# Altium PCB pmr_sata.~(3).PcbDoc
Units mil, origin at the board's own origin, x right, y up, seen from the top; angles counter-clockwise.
Board outline 6000 x 4000 mil, 2 copper layers (Top Layer, Bottom Layer); 9 components, 33 nets, 137 pads, 0 vias.
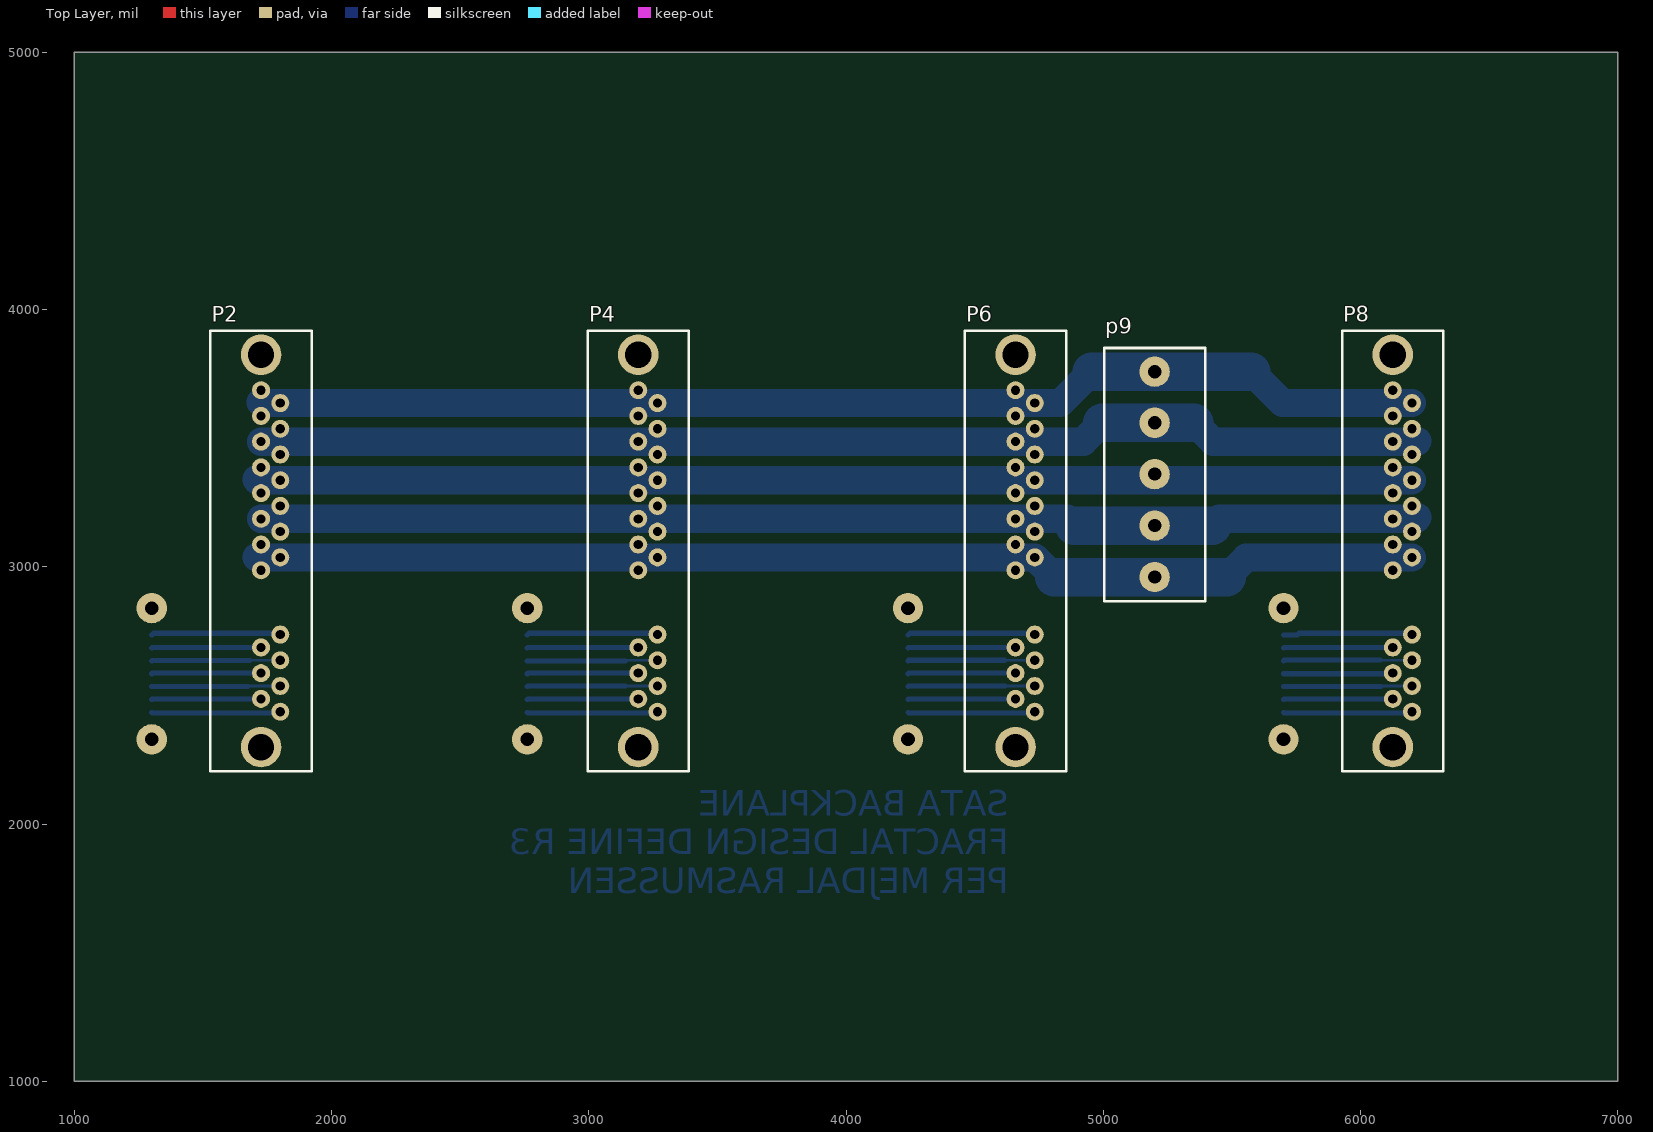
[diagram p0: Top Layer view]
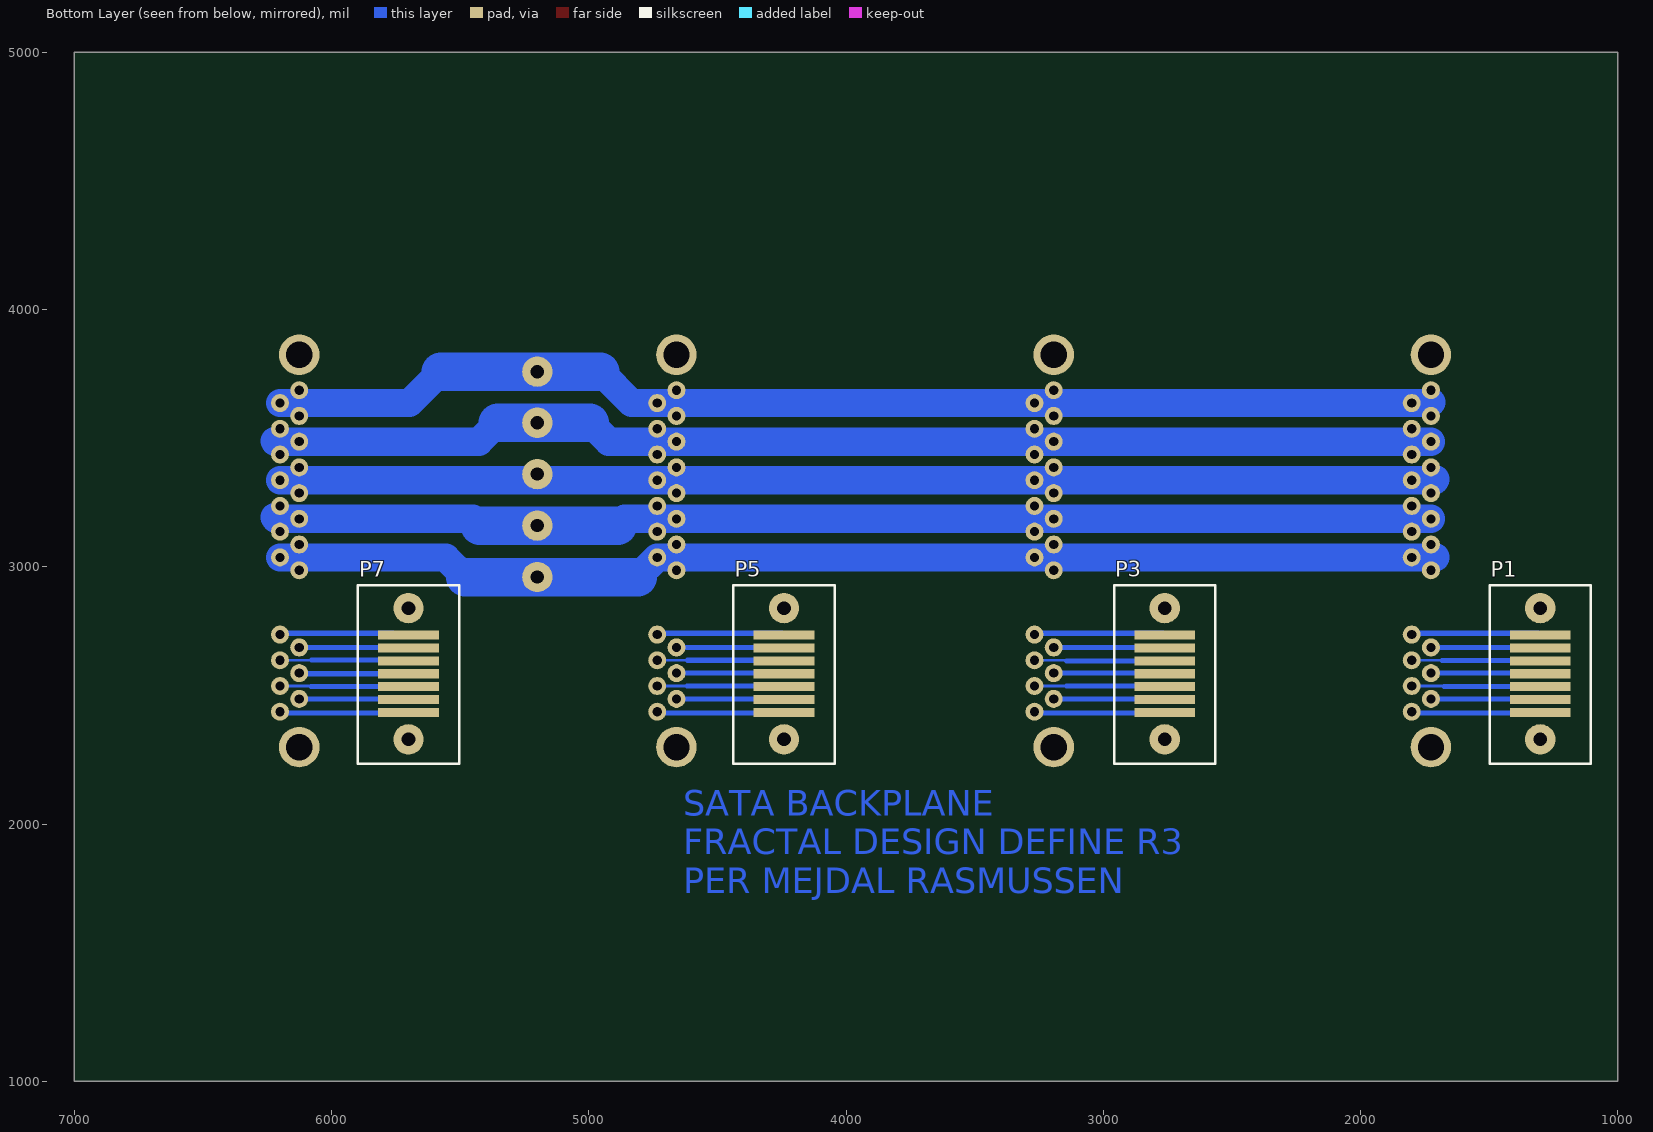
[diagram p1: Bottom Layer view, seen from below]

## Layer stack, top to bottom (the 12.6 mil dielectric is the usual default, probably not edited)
Top Layer: signal copper 1.4
Dielectric: dielectric 12.6, FR-4, Dk 4.8
Bottom Layer: signal copper 1.4

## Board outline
1000,1000 7000,1000 7000,5000 1000,5000

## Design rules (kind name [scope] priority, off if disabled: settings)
Clearance [All] p1: gap=10
PolygonConnect [All] p1: connectstyle=Relief reliefconductorwidth=10 reliefentries=4 polygonreliefangle="90 Angle"
RoomDefinition pmr_sata [InComponentClass('pmr_sata')] p1 off: confinementstyle=ConfineIn formatcopy=TRUE lockcomponents=FALSE outline 7570,1160 7280,1160 7280,1590 7570,1590
RoutingVias [All] p1: holewidth=28 width=50 viastyle="Through Hole" minholewidth=28 minwidth=50 maxholewidth=28 maxwidth=50
SilkscreenOverComponentPads [All] p1: minsilkscreentomaskgap=10
SolderMaskExpansion [All] p1: expansion=4
Width [All] p1: maxlimit=500 minlimit=10 preferedwidth=10
27 further rules are at their usual default settings.

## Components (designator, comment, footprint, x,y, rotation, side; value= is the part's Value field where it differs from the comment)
P1 "SATA lille" "pmr_sata -lille" 1301,2329 r90 bottom
P2 "SATA STOR" pmr_sata 1726,2299 r90 top
P3 "SATA lille" "pmr_sata -lille" 2761,2329 r90 bottom
P4 "SATA STOR" pmr_sata 3192.54,2299 r90 top
P5 "SATA lille" "pmr_sata -lille" 4241,2329 r90 bottom
P6 "SATA STOR" pmr_sata 4659.07,2299 r90 top
P7 "SATA lille" "pmr_sata -lille" 5701,2329 r90 bottom
P8 "SATA STOR" pmr_sata 6125.61,2299 r90 top
p9 "5polet edge" "5polet blue conn" 5200,3260 r90 top

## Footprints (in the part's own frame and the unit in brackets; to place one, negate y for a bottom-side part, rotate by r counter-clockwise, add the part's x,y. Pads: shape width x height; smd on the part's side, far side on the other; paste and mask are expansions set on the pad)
"5polet blue conn" [mm]
  round 3 hole 1.3: 1(-7.62,0) 2(-2.54,0) 3(2.54,0) 4(7.62,0) 5(12.66,0)
  silkscreen extent -10,-5 15,5
pmr_sata [mm]
  round 1.778 hole 0.9: P1(17.46,0) P2(18.73,-1.9) P3(20,0) P4(21.27,-1.9) P5(22.54,0) P6(23.81,-1.9) P7(25.08,0) P8(26.35,-1.9) P9(27.62,0) P10(28.89,-1.9) P11(30.16,0) P12(31.43,-1.9) P13(32.7,0) P14(33.97,-1.9) P15(35.24,0) S1(3.49,-1.9) S2(4.76,0) S3(6.03,-1.9) S4(7.3,0) S5(8.57,-1.9) S6(9.84,0) S7(11.11,-1.9)
  round 4 hole 2.6: S8(0,0) S8(38.74,0)
  silkscreen extent -2.4,-5 41.1,5
"pmr_sata -lille" [mm]
  rect 0.9x6 smd: S1(2.67,0) S2(3.94,0) S3(5.21,0) S4(6.48,0) S5(7.75,0) S6(9.02,0) S7(10.29,0)
  round 3 hole 1.35: S8(0,0) S8(12.96,0)
  silkscreen extent -2.4,-5 15.2,5

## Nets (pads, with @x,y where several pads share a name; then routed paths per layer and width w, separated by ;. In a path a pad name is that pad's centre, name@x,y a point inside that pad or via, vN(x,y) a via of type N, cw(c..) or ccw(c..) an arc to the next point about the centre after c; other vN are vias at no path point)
GND1: P2.P4 P2.P5 P2.P6 P4.P4 P4.P5 P4.P6 P6.P4 P6.P5 P6.P6 P8.P4 P8.P5 P8.P6 p9.2 | length 4521
  Bottom Layer w110: P2.P5 P4.P5 P6.P5 4859.6,3186.4 4877,3169 ; 5424,3159 5451.4,3186.4 P8.P5 6216.4,3186.4 6222,3192
  Bottom Layer w130: 4877,3169 4887,3159
  Bottom Layer w150: 4887,3159 5424,3159
GND2: P2.P10 P2.P11 P2.P12 P4.P10 P4.P11 P4.P12 P6.P10 P6.P11 P6.P12 P8.P10 P8.P11 P8.P12 p9.4 | length 4558
  Bottom Layer w110: P2.P11 P4.P11 P6.P11 4922.4,3486.4 4996,3560 ; 5353,3560 5426.6,3486.4 P8.P11 6219.4,3486.4 6222,3489
  Bottom Layer w150: 4996,3560 p9.4 5353,3560
NetP1_S1: P1.S1 P2.S1 | length 503
  Bottom Layer w20: P1.S1 1303.72,2431.4 1795.8,2431.4 P2.S1
NetP1_S2: P1.S2 P2.S2 | length 425.9
  Bottom Layer w20: P1.S2 1303.28,2486.4 P2.S2
NetP1_S3: P1.S3 P2.S3 | length 500.8
  Bottom Layer w10: 1675,2534 1677.4,2536.4 P2.S3
  Bottom Layer w20: P1.S3 1301.12,2534 1675,2534
NetP1_S4: P1.S4 P2.S4 | length 425.9
  Bottom Layer w20: P1.S4 1303.28,2586.4 P2.S4
NetP1_S5: P1.S5 P2.S5 | length 526.2
  Bottom Layer w10: 1683,2636 1683.4,2636.4 P2.S5
  Bottom Layer w15: P2.S5@1776,2638 1777.6,2636.4 P2.S5
  Bottom Layer w20: P1.S5 1302.88,2636 1683,2636
NetP1_S6: P1.S6 P2.S6 | length 425.9
  Bottom Layer w20: P1.S6 1303.28,2686.4 P2.S6
NetP1_S7: P1.S7 P2.S7 | length 504.9
  Bottom Layer w20: P1.S7 1308.28,2741.4 1795.8,2741.4 P2.S7
NetP3_S1: P3.S1 P4.S1 | length 509.5
  Bottom Layer w20: P3.S1 2763.72,2431.4 3262.34,2431.4 P4.S1
NetP3_S2: P3.S2 P4.S2 | length 432.5
  Bottom Layer w20: P3.S2 2763.28,2486.4 P4.S2
NetP3_S3: P3.S3 P4.S3 | length 507.3
  Bottom Layer w10: 3142,2536 3142.4,2536.4 P4.S3
  Bottom Layer w20: P3.S3 2762.88,2536 3142,2536
NetP3_S4: P3.S4 P4.S4 | length 432.5
  Bottom Layer w20: P3.S4 2763.28,2586.4 P4.S4
NetP3_S5: P3.S5 P4.S5 | length 507.4
  Bottom Layer w10: 3143,2634 3145.4,2636.4 P4.S5
  Bottom Layer w20: P3.S5 2761.12,2634 3143,2634
NetP3_S6: P3.S6 P4.S6 | length 432.5
  Bottom Layer w20: P3.S6 2763.28,2686.4 P4.S6
NetP3_S7: P3.S7 P4.S7 | length 511.4
  Bottom Layer w20: P3.S7 2768.28,2741.4 3262.34,2741.4 P4.S7
NetP5_S1: P5.S1 P6.S1 | length 496.1
  Bottom Layer w20: P5.S1 4243.72,2431.4 4728.87,2431.4 P6.S1
NetP5_S2: P5.S2 P6.S2 | length 419
  Bottom Layer w20: P5.S2 4243.28,2486.4 P6.S2
NetP5_S3: P5.S3 P6.S3 | length 494.3
  Bottom Layer w10: 4617,2537 4617.6,2536.4 P6.S3
  Bottom Layer w20: P5.S3 4243.88,2537 4617,2537
NetP5_S4: P5.S4 P6.S4 | length 419
  Bottom Layer w20: P5.S4 4243.28,2586.4 P6.S4
NetP5_S5: P5.S5 P6.S5 | length 493.8
  Bottom Layer w10: 4615.6,2636.4 P6.S5
  Bottom Layer w20: P5.S5 4243.28,2636.4 4615.6,2636.4
NetP5_S6: P5.S6 P6.S6 | length 419
  Bottom Layer w20: P5.S6 4243.28,2686.4 P6.S6
NetP5_S7: P5.S7 P6.S7 | length 498
  Bottom Layer w20: P5.S7 4248.28,2741.4 4728.87,2741.4 P6.S7
NetP7_S1: P7.S1 P8.S1 | length 502.6
  Bottom Layer w20: P7.S1 5703.72,2431.4 6195.41,2431.4 P8.S1
NetP7_S2: P7.S2 P8.S2 | length 425.6
  Bottom Layer w20: P7.S2 5703.28,2486.4 P8.S2
NetP7_S3: P7.S3 P8.S3 | length 500.4
  Bottom Layer w10: 6079,2535 6080.4,2536.4 P8.S3
  Bottom Layer w20: P7.S3 5701.88,2535 6079,2535
NetP7_S4: P7.S4 P8.S4 | length 425.6
  Bottom Layer w20: P7.S4 6123.32,2584.12 P8.S4
NetP7_S5: P7.S5 P8.S5 | length 500.9
  Bottom Layer w10: 6078,2637 6078.6,2636.4 P8.S5
  Bottom Layer w20: P7.S5 5703.88,2637 6078,2637
NetP7_S6: P7.S6 P8.S6 | length 425.6
  Bottom Layer w20: P7.S6 5703.28,2686.4 P8.S6
NetP7_S7: P7.S7 P8.S7 | length 504.5
  Bottom Layer w20: P7.S7 5754.28,2734.12 5761.57,2741.4 6195.41,2741.4 P8.S7
VCC1: P2.P1 P2.P2 P2.P3 P4.P1 P4.P2 P4.P3 P6.P1 P6.P2 P6.P3 P8.P1 P8.P2 P8.P3 p9.1 | length 4556.4
  Bottom Layer w110: 1708,3038 1709.6,3036.4 P2.P2 P4.P2 P6.P2 4810.28,2960 ; 5480,2960 5556.4,3036.4 P8.P2
  Bottom Layer w150: 4810.28,2960 p9.1 5480,2960
VCC2: P2.P7 P2.P8 P2.P9 P4.P7 P4.P8 P4.P9 P6.P7 P6.P8 P6.P9 P8.P7 P8.P8 P8.P9 p9.3 | length 4493.9
  Bottom Layer w110: 1708,3340 1711.6,3336.4 P2.P8 P4.P8 P6.P8 P8.P8
VCC3: P2.P13 P2.P14 P2.P15 P4.P13 P4.P14 P4.P15 P6.P13 P6.P14 P6.P15 P8.P13 P8.P14 P8.P15 p9.5 | length 4577.6
  Bottom Layer w110: 1725,3639 1727.6,3636.4 P2.P14 P4.P14 P6.P14 4833.4,3636.4 4955.43,3758.43 ; 5574.57,3758.43 5696.6,3636.4 P8.P14
  Bottom Layer w150: 4955.43,3758.43 p9.5 5574.57,3758.43
pads on no net: P1.S8 P2.S8 P3.S8 P4.S8 P5.S8 P6.S8 P7.S8 P8.S8

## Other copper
Bottom Layer:
  text "SATA BACKPLANE" at 4632,2033 h100
  text "FRACTAL DESIGN DEFINE R3" at 4632,1882 h100
  text "PER MEJDAL RASMUSSEN" at 4632,1731 h100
